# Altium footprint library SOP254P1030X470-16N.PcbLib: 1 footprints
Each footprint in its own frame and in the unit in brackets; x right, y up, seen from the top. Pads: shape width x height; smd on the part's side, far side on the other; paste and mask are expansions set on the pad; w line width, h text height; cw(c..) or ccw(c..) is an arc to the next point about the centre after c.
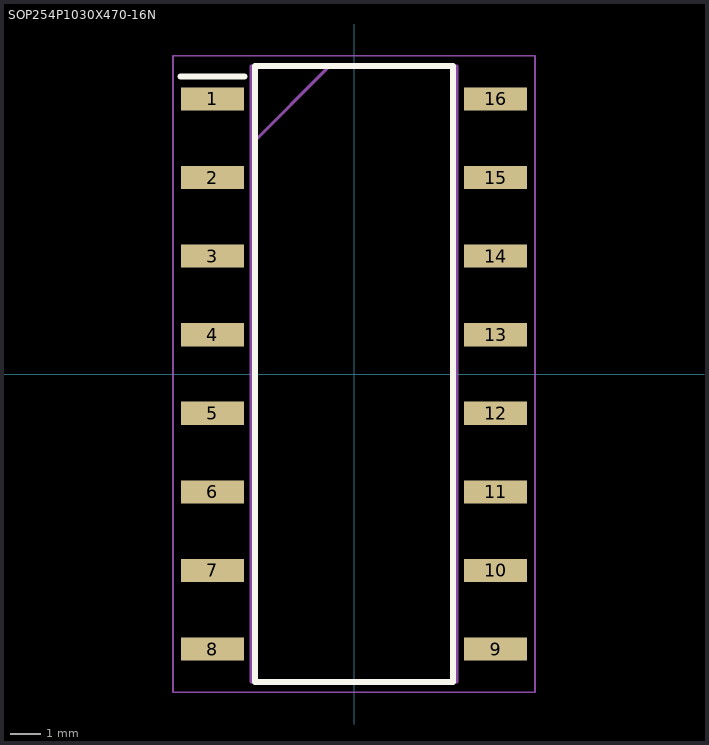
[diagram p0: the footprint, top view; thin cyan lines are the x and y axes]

## SOP254P1030X470-16N [mm]
pads (16):
  rect 2.05x0.75 smd: 1(-4.575,8.89) 2(-4.575,6.35) 3(-4.575,3.81) 4(-4.575,1.27) 5(-4.575,-1.27) 6(-4.575,-3.81) 7(-4.575,-6.35) 8(-4.575,-8.89) 9(4.575,-8.89) 10(4.575,-6.35) 11(4.575,-3.81) 12(4.575,-1.27) 13(4.575,1.27) 14(4.575,3.81) 15(4.575,6.35) 16(4.575,8.89)
Top Overlay:
  lines w0.2: -5.6,9.615 -3.55,9.615 ; -3.2,-9.96 3.2,-9.96 3.2,9.96 -3.2,9.96 -3.2,-9.96
Mechanical 15:
  lines w0.1: -3.322,7.42 -0.782,9.96 ; -3.322,-9.96 3.322,-9.96 3.322,9.96 -3.322,9.96 -3.322,-9.96
Mechanical 20:
  lines w0.05: -5.85,-10.285 5.85,-10.285 5.85,10.285 -5.85,10.285 -5.85,-10.285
